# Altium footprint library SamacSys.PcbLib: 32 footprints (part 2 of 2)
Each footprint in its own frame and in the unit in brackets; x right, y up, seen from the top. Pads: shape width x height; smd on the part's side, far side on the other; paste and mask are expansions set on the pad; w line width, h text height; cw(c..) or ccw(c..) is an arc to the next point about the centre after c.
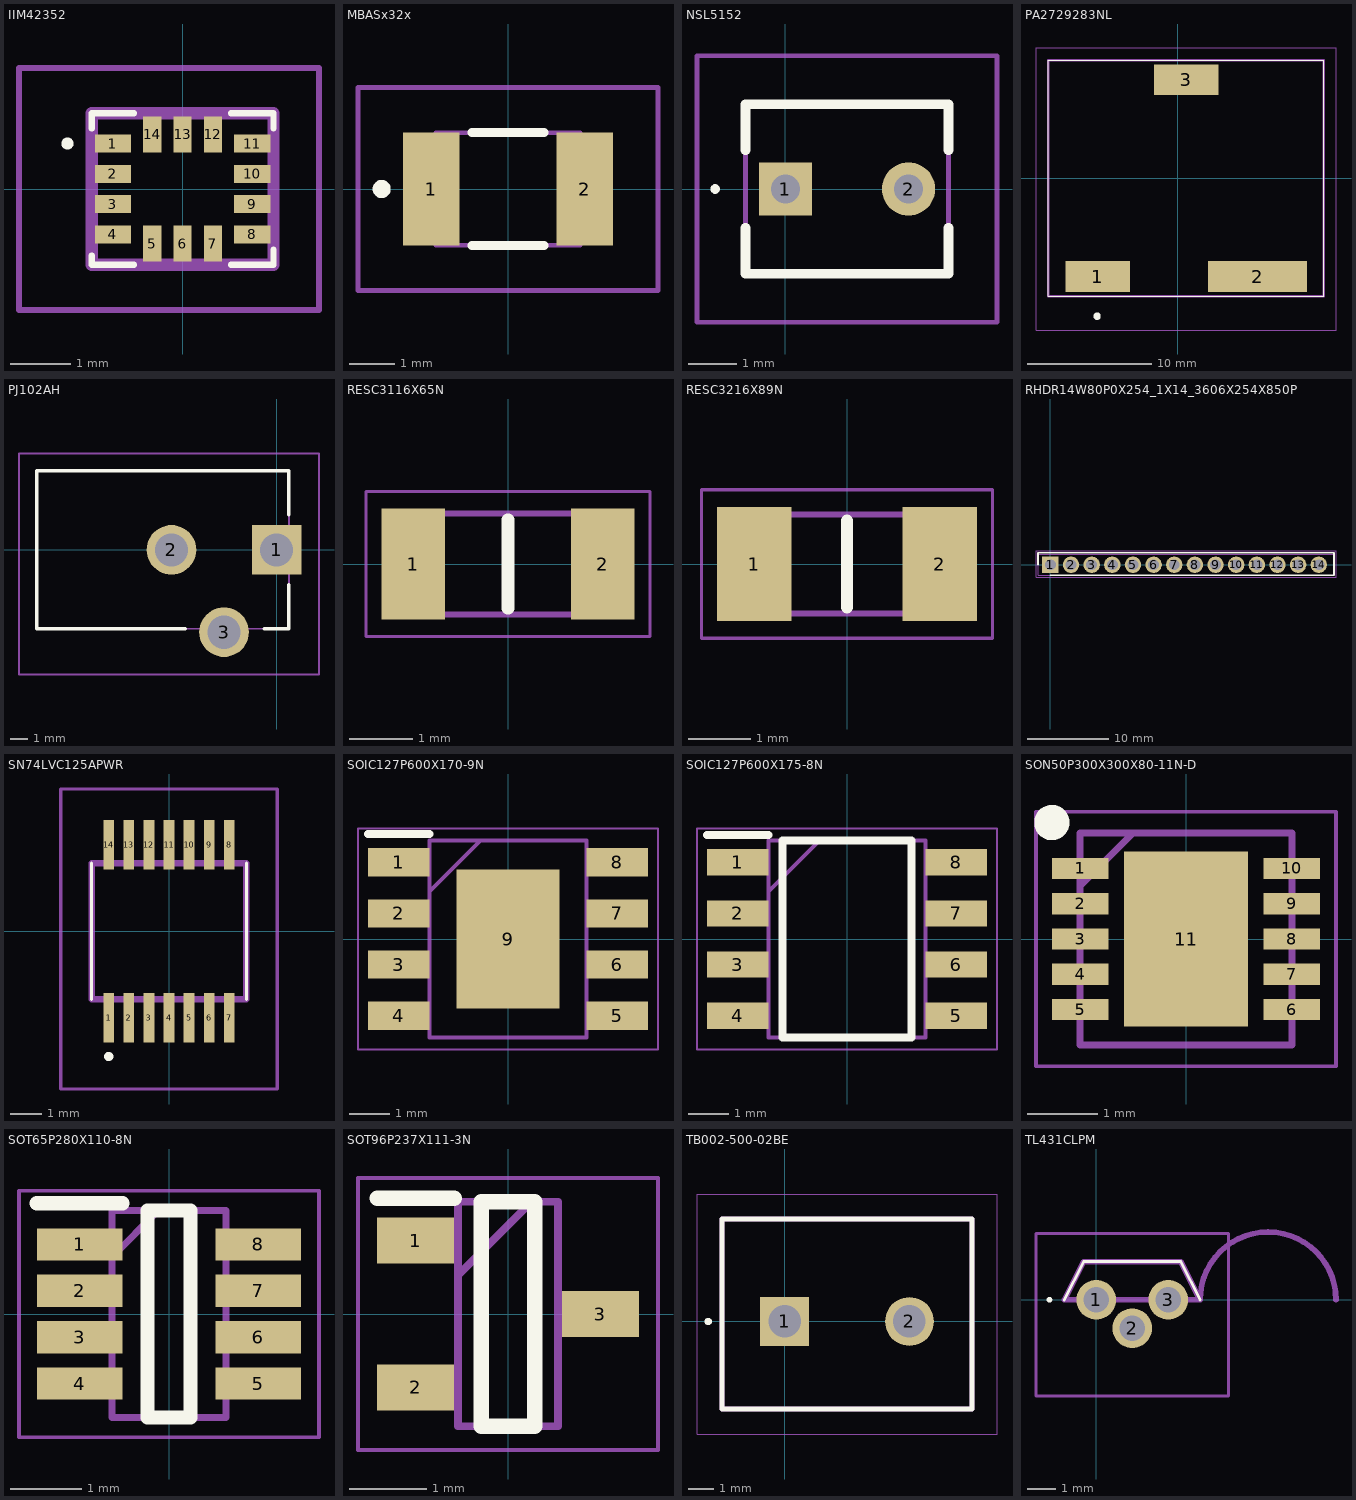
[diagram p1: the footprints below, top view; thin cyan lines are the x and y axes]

## IIM42352 [mm]
pads (14):
  rect 0.6x0.3 smd: 1(-1.15,0.75) 2(-1.15,0.25) 3(-1.15,-0.25) 4(-1.15,-0.75) 8(1.15,-0.75) 9(1.15,-0.25) 10(1.15,0.25) 11(1.15,0.75)
  rect 0.3x0.6 smd: 5(-0.5,-0.9) 6(0,-0.9) 7(0.5,-0.9) 12(0.5,0.9) 13(0,0.9) 14(-0.5,0.9)
Top Overlay:
  lines w0.1: -1.5,-1.1 -1.5,-1.25 -0.8,-1.25 ; -1.5,1 -1.5,1.25 -0.8,1.25 ; 0.8,-1.25 1.5,-1.25 1.5,-1 ; 0.8,1.25 1.5,1.25 1.5,1 ; -1.9,0.7 cw(c-1.9,0.75) -1.9,0.8 cw(c-1.9,0.75) -1.9,0.7
Mechanical 13:
  lines w0.2: -1.5,-1.25 1.5,-1.25 1.5,1.25 -1.5,1.25 -1.5,-1.25
Mechanical 15:
  lines w0.1: -2.7,-2 2.25,-2 2.25,2 -2.7,2 -2.7,-2
3D body "ICM-42688-P.stp": height 0.9, standoff -0.01, extent -1.5,-1.25 1.5,1.25

## MBASx32x [mm]
pads (2):
  rect 1.25x2.5 smd: 1(-1.7,0) 2(1.7,0)
Top Overlay:
  lines w0.2: -0.8,-1.25 0.8,-1.25 ; -0.8,1.25 0.8,1.25 ; -2.8,-0.1 ccw(c-2.8,0) -2.8,0.1 ccw(c-2.8,0) -2.8,-0.1
Mechanical 13:
  lines w0.1: -1.6,-1.25 -1.6,1.25 1.6,1.25 1.6,-1.25 -1.6,-1.25
Mechanical 15:
  lines w0.1: -3.325,-2.25 -3.325,2.25 3.325,2.25 3.325,-2.25 -3.325,-2.25
3D body "MBASJ32MAB5107MPNA01.stp": height 2.6, standoff 0, extent -2.2,-1.25 2.2,1.25

## NSL5152 [mm]
pads (2):
  rect 1.1x1.1 hole 0.6: 1(0,0)
  round 1.1 hole 0.6: 2(2.54,0)
Top Overlay:
  lines w0.1: -1.5,0 cw(c-1.45,0) -1.4,0 cw(c-1.45,0) -1.5,0
  lines w0.2: -0.825,-0.8 -0.825,-1.75 3.365,-1.75 3.365,-0.8 ; -0.825,0.8 -0.825,1.75 3.365,1.75 3.365,0.8
Mechanical 13:
  lines w0.1: -0.825,-1.75 -0.825,1.75 3.365,1.75 3.365,-1.75 -0.825,-1.75
Mechanical 15:
  lines w0.1: -1.825,-2.75 -1.825,2.75 4.365,2.75 4.365,-2.75 -1.825,-2.75
3D body "NSL-5152.stp": height 2.48, standoff -5, extent -0.825,-1.75 3.365,1.75

## PA2729283NL [mm]
pads (3):
  rect 5.2x2.5 smd: 1(-6.45,-7.95) 3(0.7,7.95)
  rect 8x2.5 smd: 2(6.477,-7.95)
Top Overlay:
  lines w0.1: -10.43,-9.525 11.8,-9.525 11.8,9.525 -10.43,9.525 -10.43,-9.525
  lines w0.3: -6.5,-11.3 cw(c-6.5,-11.15) -6.5,-11 cw(c-6.5,-11.15) -6.5,-11.3
Mechanical 13:
  lines w0.2: -10.43,-9.525 11.8,-9.525 11.8,9.525 -10.43,9.525 -10.43,-9.525
Mechanical 15:
  lines w0.1: -11.43,-12.3 12.8,-12.3 12.8,10.525 -11.43,10.525 -11.43,-12.3
3D body "PA2729.283NL.stp": height 12.3, standoff 0, extent -10.43,-9.525 11.8,9.525

## PJ102AH [mm]
pads (3):
  rect 2.835x2.835 hole 1.89: 1(0,0)
  round 2.835 hole 1.89: 2(-6,0) 3(-3,-4.7)
Top Overlay:
  lines w0.2: -5.2,-4.5 -13.7,-4.5 -13.7,4.5 0.7,4.5 0.7,2 ; -0.7,-4.5 0.7,-4.5 0.7,-2
Mechanical 13:
  lines w0.1: -13.7,-4.5 -13.7,4.5 0.7,4.5 0.7,-4.5 -13.7,-4.5
Mechanical 15:
  lines w0.1: -14.7,-7.118 -14.7,5.5 2.418,5.5 2.418,-7.118 -14.7,-7.118
3D body "PJ-102AH.stp": height 11.5, standoff -3, extent -13.7,-4.9 0.7,4.5

## RESC3116X65N [mm]
pads (2):
  rect 1x1.75 smd: 1(-1.5,0) 2(1.5,0)
Top Overlay:
  lines w0.2: 0,-0.7 0,0.7
Mechanical 13:
  lines w0.1: -1.55,-0.8 -1.55,0.8 1.55,0.8 1.55,-0.8 -1.55,-0.8
Mechanical 15:
  lines w0.05: -2.25,-1.15 -2.25,1.15 2.25,1.15 2.25,-1.15 -2.25,-1.15
3D body "RT1206FRE0768KL.stp": height 0.65, standoff 0, extent -1.55,-0.8 1.55,0.8

## RESC3216X89N [mm]
pads (2):
  rect 1.2x1.85 smd: 1(-1.5,0) 2(1.5,0)
Top Overlay:
  lines w0.2: 0,-0.7 0,0.7
Mechanical 13:
  lines w0.1: -1.6,-0.8 -1.6,0.8 1.6,0.8 1.6,-0.8 -1.6,-0.8
Mechanical 15:
  lines w0.05: -2.35,-1.2 -2.35,1.2 2.35,1.2 2.35,-1.2 -2.35,-1.2
3D body "WSLP1206R0500DEA.stp": height 0.64, standoff 0, extent -1.6,-0.8 1.6,0.8

## RHDR14W80P0X254_1X14_3606X254X850P [mm]
pads (14):
  rect 2.025x2.025 hole 1.35: 1(0,0)
  round 2.025 hole 1.35: 2(2.54,0) 3(5.08,0) 4(7.62,0) 5(10.16,0) 6(12.7,0) 7(15.24,0) 8(17.78,0) 9(20.32,0) 10(22.86,0) 11(25.4,0) 12(27.94,0) 13(30.48,0) 14(33.02,0)
Top Overlay:
  lines w0.2: -1.52,0 -1.52,1.455 34.89,1.455 34.89,-1.27 0,-1.27
Mechanical 13:
  lines w0.1: -1.52,-1.27 -1.52,1.27 34.89,1.27 34.89,-1.27 -1.52,-1.27
Mechanical 15:
  lines w0.05: -1.77,-1.52 -1.77,1.705 35.14,1.705 35.14,-1.52 -1.77,-1.52
3D body "PPTC141LFBN-RC.stp": height 8.5, standoff -3.5, extent -1.52,-1.27 34.54,1.27

## SN74LVC125APWR [mm]
pads (14):
  rect 0.35x1.6 smd: 1(-1.95,-2.8) 2(-1.3,-2.8) 3(-0.65,-2.8) 4(0,-2.8) 5(0.65,-2.8) 6(1.3,-2.8) 7(1.95,-2.8) 8(1.95,2.8) 9(1.3,2.8) 10(0.65,2.8) 11(0,2.8) 12(-0.65,2.8) 13(-1.3,2.8) 14(-1.95,2.8)
Top Overlay:
  lines w0.1: -2.5,-2.2 -2.5,2.2 ; 2.5,-2.2 2.5,2.2
  lines w0.2: -1.95,-4.1 ccw(c-1.95,-4.05) -1.95,-4 ccw(c-1.95,-4.05) -1.95,-4.1
Mechanical 13:
  lines w0.2: -2.5,-2.2 -2.5,2.2 2.5,2.2 2.5,-2.2 -2.5,-2.2
Mechanical 15:
  lines w0.1: -3.5,-5.1 -3.5,4.6 3.5,4.6 3.5,-5.1 -3.5,-5.1
3D body "SN74LVC125APWR.stp": height 1.13, standoff 0, extent -2.5,-3.2 2.5,3.2

## SOIC127P600X170-9N [mm]
pads (9):
  rect 1.525x0.7 smd: 1(-2.712,1.905) 2(-2.712,0.635) 3(-2.712,-0.635) 4(-2.712,-1.905) 5(2.712,-1.905) 6(2.712,-0.635) 7(2.712,0.635) 8(2.712,1.905)
  rect 2.56x3.45 smd: 9(0,0)
Top Overlay:
  lines w0.2: -3.475,2.605 -1.95,2.605
Mechanical 13:
  lines w0.1: -1.95,1.18 -0.68,2.45 ; -1.95,-2.45 -1.95,2.45 1.95,2.45 1.95,-2.45 -1.95,-2.45
Mechanical 15:
  lines w0.05: -3.725,-2.75 -3.725,2.75 3.725,2.75 3.725,-2.75 -3.725,-2.75
3D body "MP9486AGN-Z.stp": height 1.7, standoff 0, extent -3,-2.45 3,2.45

## SOIC127P600X175-8N [mm]
pads (8):
  rect 1.525x0.65 smd: 1(-2.712,1.905) 2(-2.712,0.635) 3(-2.712,-0.635) 4(-2.712,-1.905) 5(2.712,-1.905) 6(2.712,-0.635) 7(2.712,0.635) 8(2.712,1.905)
Top Overlay:
  lines w0.2: -3.475,2.58 -1.95,2.58 ; -1.6,-2.45 1.6,-2.45 1.6,2.45 -1.6,2.45 -1.6,-2.45
Mechanical 13:
  lines w0.1: -1.95,1.18 -0.68,2.45 ; -1.95,-2.45 1.95,-2.45 1.95,2.45 -1.95,2.45 -1.95,-2.45
Mechanical 15:
  lines w0.05: -3.725,-2.75 3.725,-2.75 3.725,2.75 -3.725,2.75 -3.725,-2.75
3D body "NE555DR.stp": height 1.75, standoff 0, extent -3,-2.45 3,2.45

## SON50P300X300X80-11N-D [mm]
pads (11):
  rect 0.8x0.3 smd: 1(-1.5,1) 2(-1.5,0.5) 3(-1.5,0) 4(-1.5,-0.5) 5(-1.5,-1) 6(1.5,-1) 7(1.5,-0.5) 8(1.5,0) 9(1.5,0.5) 10(1.5,1)
  rect 1.75x2.48 smd: 11(0,0)
Top Overlay:
  circle w0.25: c-1.9,1.65 r0.125
Mechanical 13:
  lines w0.1: -1.5,0.75 -0.75,1.5 ; -1.5,-1.5 -1.5,1.5 1.5,1.5 1.5,-1.5 -1.5,-1.5
Mechanical 15:
  lines w0.05: -2.125,-1.8 -2.125,1.8 2.125,1.8 2.125,-1.8 -2.125,-1.8
3D body "LT8333RDD#TRPBF.stp": height 0.8, standoff 0, extent -1.55,-1.5 1.55,1.5

## SOT65P280X110-8N [mm]
pads (8):
  rect 1.2x0.45 smd: 1(-1.25,0.975) 2(-1.25,0.325) 3(-1.25,-0.325) 4(-1.25,-0.975) 5(1.25,-0.975) 6(1.25,-0.325) 7(1.25,0.325) 8(1.25,0.975)
Top Overlay:
  lines w0.2: -1.85,1.55 -0.65,1.55 ; -0.3,-1.45 -0.3,1.45 0.3,1.45 0.3,-1.45 -0.3,-1.45
Mechanical 13:
  lines w0.1: -0.8,0.8 -0.15,1.45 ; -0.8,-1.45 -0.8,1.45 0.8,1.45 0.8,-1.45 -0.8,-1.45
Mechanical 15:
  lines w0.05: -2.1,-1.725 -2.1,1.725 2.1,1.725 2.1,-1.725 -2.1,-1.725
3D body "INA296A3IDDFR.stp": height 1.1, standoff 0, extent -1.4,-1.45 1.4,1.45

## SOT96P237X111-3N [mm]
pads (3):
  rect 1x0.6 smd: 1(-1.2,0.955) 2(-1.2,-0.955) 3(1.2,0)
Top Overlay:
  lines w0.2: -1.7,1.505 -0.7,1.505 ; -0.35,-1.46 -0.35,1.46 0.35,1.46 0.35,-1.46 -0.35,-1.46
Mechanical 13:
  lines w0.1: -0.65,0.505 0.305,1.46 ; -0.65,-1.46 -0.65,1.46 0.65,1.46 0.65,-1.46 -0.65,-1.46
Mechanical 15:
  lines w0.05: -1.95,-1.77 -1.95,1.77 1.95,1.77 1.95,-1.77 -1.95,-1.77
3D body "BZX84C3V0LT1G.stp": height 1.11, standoff 0, extent -1.185,-1.46 1.185,1.46

## TB002-500-02BE [mm]
pads (2):
  rect 1.95x1.95 hole 1.3: 1(0,0)
  round 1.95 hole 1.3: 2(5,0)
Top Overlay:
  circle w0.2: c-3.05,0 r0.05
  lines w0.2: -2.5,-3.5 -2.5,4.1 7.5,4.1 7.5,-3.5 -2.5,-3.5
Mechanical 13:
  lines w0.2: -2.5,-3.5 -2.5,4.1 7.5,4.1 7.5,-3.5 -2.5,-3.5
Mechanical 15:
  lines w0.05: -3.5,-4.5 -3.5,5.1 8.5,5.1 8.5,-4.5 -3.5,-4.5
3D body "TB002-500-02BE.stp": height 10, standoff -4.35, extent -2.53,-4.16 7.97,3.44

## TL431CLPM [mm]
pads (3):
  round 1.4 hole 0.9: 1(0,0) 2(1.27,-1) 3(2.54,0)
Top Overlay:
  lines w0.1: -1.13,0 -0.445,1.35 2.985,1.35 3.67,0 ; -1.707,0.005 cw(c-1.656,0.005) -1.605,0.005 cw(c-1.656,0.005) -1.707,0.005
Mechanical 13:
  lines w0.2: 8.47,0 ccw(c6.07,0) 3.67,0 ; -0.445,1.35 2.985,1.35 ; -0.445,1.35 2.985,1.35 ; -0.445,1.35 -1.13,0 3.67,0 ; 2.985,1.35 3.67,0
Mechanical 15:
  lines w0.1: -2.13,-3.4 4.67,-3.4 4.67,2.35 -2.13,2.35 -2.13,-3.4
3D body "LP2950-33LPRE3.stp": height 4.91, standoff -12.62, extent -1.13,-2.222 3.695,1.46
